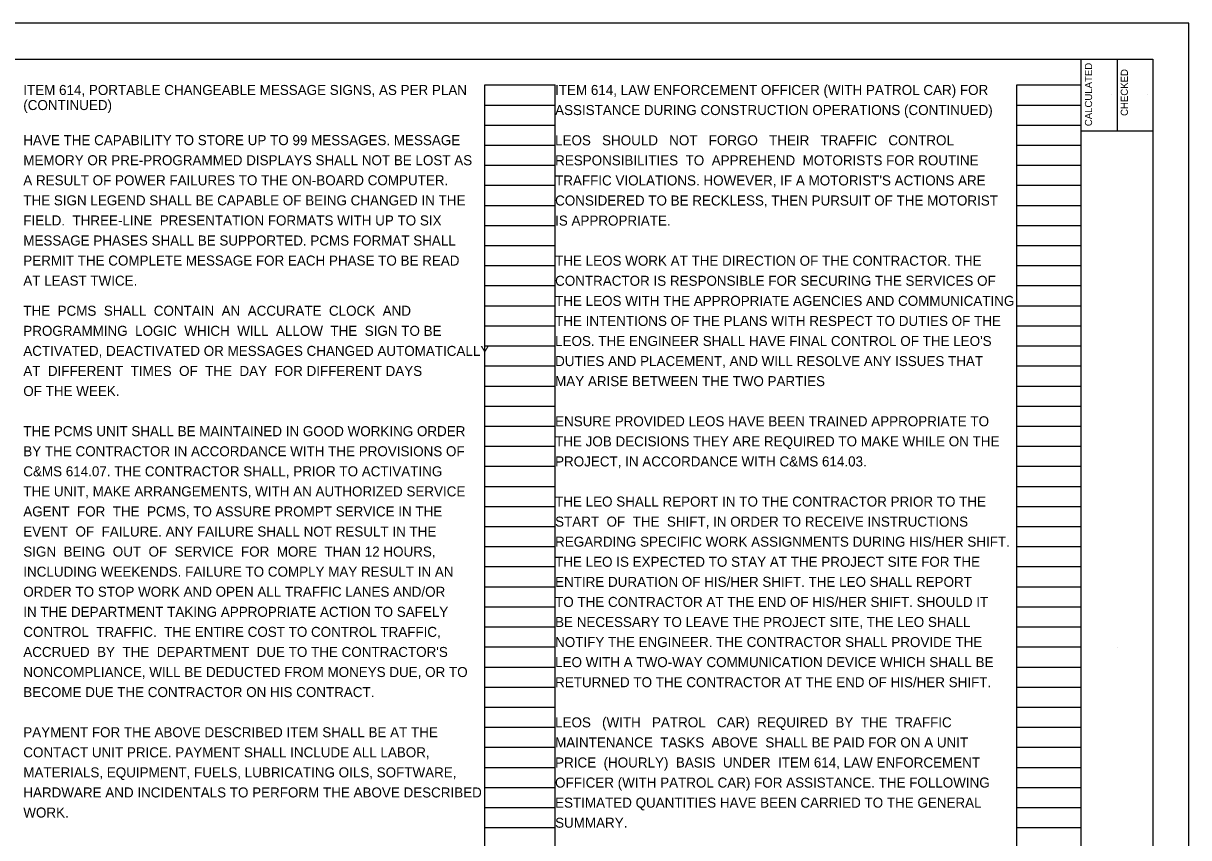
# Model space of a CAD drawing. Extents: x -51 to 34, y 0 to 22.
# Drawn here: x 17.74 to 34, y 10.64 to 22 of the extents above; entities that cross this region are included whole.
import ezdxf

# ---------------------------------------------------------------- set-up
doc = ezdxf.new("R2010")
doc.units = 0
for name, color, linetype in [('SH_Border', 7, 'Continuous'), ('SH_Cut_Line', 7, 'Continuous'), ('SH_Data', 7, 'Continuous'), ('SH_Text', 7, 'Continuous')]:
    doc.layers.add(name, color=color, linetype=linetype)

msp = doc.modelspace()

# ---------------------------------------------------------------- linework, layer by layer
at = {"layer": 'SH_Border'}
for p, q in [((32.5, 0.5), (32.5, 21.5)), ((33, 21.5), (33, 20.5)), ((32.5, 20.5), (33.5, 20.5))]:
    msp.add_line(p, q, dxfattribs=at)
msp.add_lwpolyline([(2, 21.5), (33.5, 21.5), (33.5, 0.5), (2, 0.5)], close=True, dxfattribs=at)
at = {"layer": 'SH_Cut_Line'}
msp.add_lwpolyline([(0, 0), (34, 0), (34, 22), (0, 22)], close=True, dxfattribs=at)
at = {"layer": 'SH_Data'}
for p, q in [((24.18, 0.98), (24.18, 21.14)), ((24.18, 21.14), (25.16, 21.14)), ((25.16, 0.98), (25.16, 21.14)), ((31.6, 0.98), (31.6, 21.14)), ((31.6, 21.14), (32.5, 21.14)), ((32.5, 0.98), (32.5, 21.14)), ((32.92, 21.004), (32.92, 21.004)), ((33.42, 21.004), (33.42, 21.004)), ((24.18, 20.86), (25.16, 20.86)), ((31.6, 20.86), (32.5, 20.86)), ((24.18, 20.58), (25.16, 20.58)), ((31.6, 20.58), (32.5, 20.58)), ((24.18, 20.3), (25.16, 20.3)), ((31.6, 20.3), (32.5, 20.3)), ((24.18, 20.02), (25.16, 20.02)), ((31.6, 20.02), (32.5, 20.02)), ((24.18, 19.74), (25.16, 19.74)), ((31.6, 19.74), (32.5, 19.74)), ((24.18, 19.46), (25.16, 19.46)), ((31.6, 19.46), (32.5, 19.46)), ((24.18, 19.18), (25.16, 19.18)), ((31.6, 19.18), (32.5, 19.18)), ((24.18, 18.9), (25.16, 18.9)), ((31.6, 18.9), (32.5, 18.9)), ((24.18, 18.62), (25.16, 18.62)), ((31.6, 18.62), (32.5, 18.62)), ((24.18, 18.34), (25.16, 18.34)), ((31.6, 18.34), (32.5, 18.34)), ((24.18, 18.06), (25.16, 18.06)), ((31.6, 18.06), (32.5, 18.06)), ((24.18, 17.78), (25.16, 17.78)), ((31.6, 17.78), (32.5, 17.78)), ((24.18, 17.5), (25.16, 17.5)), ((31.6, 17.5), (32.5, 17.5)), ((24.18, 17.22), (25.16, 17.22)), ((31.6, 17.22), (32.5, 17.22)), ((24.18, 16.94), (25.16, 16.94)), ((31.6, 16.94), (32.5, 16.94)), ((24.18, 16.66), (25.16, 16.66)), ((31.6, 16.66), (32.5, 16.66)), ((24.18, 16.38), (25.16, 16.38)), ((31.6, 16.38), (32.5, 16.38)), ((24.18, 16.1), (25.16, 16.1)), ((31.6, 16.1), (32.5, 16.1)), ((24.18, 15.82), (25.16, 15.82)), ((31.6, 15.82), (32.5, 15.82)), ((24.18, 15.54), (25.16, 15.54)), ((31.6, 15.54), (32.5, 15.54)), ((24.18, 15.26), (25.16, 15.26)), ((31.6, 15.26), (32.5, 15.26)), ((24.18, 14.98), (25.16, 14.98)), ((31.6, 14.98), (32.5, 14.98)), ((24.18, 14.7), (25.16, 14.7)), ((31.6, 14.7), (32.5, 14.7)), ((24.18, 14.42), (25.16, 14.42)), ((31.6, 14.42), (32.5, 14.42)), ((24.18, 14.14), (25.16, 14.14)), ((31.6, 14.14), (32.5, 14.14)), ((24.18, 13.86), (25.16, 13.86)), ((31.6, 13.86), (32.5, 13.86)), ((24.18, 13.58), (25.16, 13.58)), ((31.6, 13.58), (32.5, 13.58)), ((24.18, 13.3), (25.16, 13.3)), ((31.6, 13.3), (32.5, 13.3)), ((33, 13.292), (33, 13.292)), ((24.18, 13.02), (25.16, 13.02)), ((31.6, 13.02), (32.5, 13.02)), ((24.18, 12.74), (25.16, 12.74)), ((31.6, 12.74), (32.5, 12.74)), ((24.18, 12.46), (25.16, 12.46)), ((31.6, 12.46), (32.5, 12.46)), ((24.18, 12.18), (25.16, 12.18)), ((31.6, 12.18), (32.5, 12.18)), ((24.18, 11.9), (25.16, 11.9)), ((31.6, 11.9), (32.5, 11.9)), ((24.18, 11.62), (25.16, 11.62)), ((31.6, 11.62), (32.5, 11.62)), ((24.18, 11.34), (25.16, 11.34)), ((31.6, 11.34), (32.5, 11.34)), ((24.18, 11.06), (25.16, 11.06)), ((31.6, 11.06), (32.5, 11.06)), ((24.18, 10.78), (25.16, 10.78)), ((31.6, 10.78), (32.5, 10.78))]:
    msp.add_line(p, q, dxfattribs=at)

# ---------------------------------------------------------------- texts
for s, p in [('CALCULATED', (32.652, 20.565)), ('CHECKED', (33.152, 20.708))]:
    msp.add_text(s, height=0.1, rotation=90, dxfattribs=at).set_placement(p)
at = {"layer": 'SH_Text'}
for s, p in [('ITEM 614, PORTABLE CHANGEABLE MESSAGE SIGNS, AS PER PLAN', (17.74, 21)), ('ITEM 614, LAW ENFORCEMENT OFFICER (WITH PATROL CAR) FOR', (25.16, 21)), ('(CONTINUED)', (17.74, 20.79)), ('ASSISTANCE DURING CONSTRUCTION OPERATIONS (CONTINUED)', (25.16, 20.72)), ('HAVE THE CAPABILITY TO STORE UP TO 99 MESSAGES. MESSAGE', (17.74, 20.3)), ('LEOS   SHOULD   NOT   FORGO   THEIR   TRAFFIC   CONTROL', (25.16, 20.298)), ('MEMORY OR PRE-PROGRAMMED DISPLAYS SHALL NOT BE LOST AS', (17.74, 20.02)), ('RESPONSIBILITIES  TO  APPREHEND  MOTORISTS FOR ROUTINE', (25.16, 20.018)), ('A RESULT OF POWER FAILURES TO THE ON-BOARD COMPUTER.', (17.74, 19.74)), ("TRAFFIC VIOLATIONS. HOWEVER, IF A MOTORIST'S ACTIONS ARE", (25.16, 19.738)), ('THE SIGN LEGEND SHALL BE CAPABLE OF BEING CHANGED IN THE', (17.74, 19.46)), ('CONSIDERED TO BE RECKLESS, THEN PURSUIT OF THE MOTORIST', (25.16, 19.458)), ('FIELD.  THREE-LINE  PRESENTATION FORMATS WITH UP TO SIX', (17.74, 19.18)), ('IS APPROPRIATE.', (25.16, 19.178)), ('MESSAGE PHASES SHALL BE SUPPORTED. PCMS FORMAT SHALL', (17.74, 18.9)), ('PERMIT THE COMPLETE MESSAGE FOR EACH PHASE TO BE READ', (17.74, 18.62)), ('THE LEOS WORK AT THE DIRECTION OF THE CONTRACTOR. THE', (25.16, 18.618)), ('AT LEAST TWICE.', (17.74, 18.34)), ('CONTRACTOR IS RESPONSIBLE FOR SECURING THE SERVICES OF', (25.16, 18.338)), ('THE  PCMS  SHALL  CONTAIN  AN  ACCURATE  CLOCK  AND', (17.74, 17.92)), ('THE LEOS WITH THE APPROPRIATE AGENCIES AND COMMUNICATING', (25.16, 18.058)), ('THE INTENTIONS OF THE PLANS WITH RESPECT TO DUTIES OF THE', (25.16, 17.778)), ('PROGRAMMING  LOGIC  WHICH  WILL  ALLOW  THE  SIGN TO BE', (17.74, 17.64)), ("LEOS. THE ENGINEER SHALL HAVE FINAL CONTROL OF THE LEO'S", (25.16, 17.498)), ('ACTIVATED, DEACTIVATED OR MESSAGES CHANGED AUTOMATICALLY', (17.74, 17.36)), ('DUTIES AND PLACEMENT, AND WILL RESOLVE ANY ISSUES THAT', (25.16, 17.218)), ('AT  DIFFERENT  TIMES  OF  THE  DAY  FOR DIFFERENT DAYS', (17.74, 17.08)), ('MAY ARISE BETWEEN THE TWO PARTIES', (25.16, 16.938)), ('OF THE WEEK.', (17.74, 16.8)), ('ENSURE PROVIDED LEOS HAVE BEEN TRAINED APPROPRIATE TO', (25.16, 16.378)), ('THE PCMS UNIT SHALL BE MAINTAINED IN GOOD WORKING ORDER', (17.74, 16.24)), ('BY THE CONTRACTOR IN ACCORDANCE WITH THE PROVISIONS OF', (17.74, 15.96)), ('THE JOB DECISIONS THEY ARE REQUIRED TO MAKE WHILE ON THE', (25.16, 16.098)), ('PROJECT, IN ACCORDANCE WITH C&MS 614.03.', (25.16, 15.818)), ('C&MS 614.07. THE CONTRACTOR SHALL, PRIOR TO ACTIVATING', (17.74, 15.68)), ('THE UNIT, MAKE ARRANGEMENTS, WITH AN AUTHORIZED SERVICE', (17.74, 15.4)), ('THE LEO SHALL REPORT IN TO THE CONTRACTOR PRIOR TO THE', (25.16, 15.258)), ('AGENT  FOR  THE  PCMS, TO ASSURE PROMPT SERVICE IN THE', (17.74, 15.12)), ('EVENT  OF  FAILURE. ANY FAILURE SHALL NOT RESULT IN THE', (17.74, 14.84)), ('START  OF  THE  SHIFT, IN ORDER TO RECEIVE INSTRUCTIONS', (25.16, 14.978)), ('REGARDING SPECIFIC WORK ASSIGNMENTS DURING HIS/HER SHIFT.', (25.16, 14.698)), ('SIGN  BEING  OUT  OF  SERVICE  FOR  MORE  THAN 12 HOURS,', (17.74, 14.56)), ('THE LEO IS EXPECTED TO STAY AT THE PROJECT SITE FOR THE', (25.16, 14.418)), ('INCLUDING WEEKENDS. FAILURE TO COMPLY MAY RESULT IN AN', (17.74, 14.28)), ('ORDER TO STOP WORK AND OPEN ALL TRAFFIC LANES AND/OR', (17.74, 14)), ('ENTIRE DURATION OF HIS/HER SHIFT. THE LEO SHALL REPORT', (25.16, 14.138)), ('TO THE CONTRACTOR AT THE END OF HIS/HER SHIFT. SHOULD IT', (25.16, 13.858)), ('IN THE DEPARTMENT TAKING APPROPRIATE ACTION TO SAFELY', (17.74, 13.72)), ('BE NECESSARY TO LEAVE THE PROJECT SITE, THE LEO SHALL', (25.16, 13.578)), ('CONTROL  TRAFFIC.  THE ENTIRE COST TO CONTROL TRAFFIC,', (17.74, 13.44)), ('NOTIFY THE ENGINEER. THE CONTRACTOR SHALL PROVIDE THE', (25.16, 13.298)), ("ACCRUED  BY  THE  DEPARTMENT  DUE TO THE CONTRACTOR'S", (17.74, 13.16)), ('NONCOMPLIANCE, WILL BE DEDUCTED FROM MONEYS DUE, OR TO', (17.74, 12.88)), ('LEO WITH A TWO-WAY COMMUNICATION DEVICE WHICH SHALL BE', (25.16, 13.018)), ('RETURNED TO THE CONTRACTOR AT THE END OF HIS/HER SHIFT.', (25.16, 12.738)), ('BECOME DUE THE CONTRACTOR ON HIS CONTRACT.', (17.74, 12.6)), ('LEOS   (WITH   PATROL   CAR)  REQUIRED  BY  THE  TRAFFIC', (25.16, 12.178)), ('PAYMENT FOR THE ABOVE DESCRIBED ITEM SHALL BE AT THE ', (17.74, 12.04)), ('MAINTENANCE  TASKS  ABOVE  SHALL BE PAID FOR ON A UNIT', (25.16, 11.898)), ('CONTACT UNIT PRICE. PAYMENT SHALL INCLUDE ALL LABOR,', (17.74, 11.76)), ('PRICE  (HOURLY)  BASIS  UNDER  ITEM 614, LAW ENFORCEMENT', (25.16, 11.618)), ('MATERIALS, EQUIPMENT, FUELS, LUBRICATING OILS, SOFTWARE,', (17.74, 11.48)), ('OFFICER (WITH PATROL CAR) FOR ASSISTANCE. THE FOLLOWING', (25.16, 11.338)), ('HARDWARE AND INCIDENTALS TO PERFORM THE ABOVE DESCRIBED', (17.74, 11.2)), ('WORK.', (17.74, 10.92)), ('ESTIMATED QUANTITIES HAVE BEEN CARRIED TO THE GENERAL', (25.16, 11.058)), ('SUMMARY.', (25.16, 10.778))]:
    msp.add_text(s, height=0.14, dxfattribs=at).set_placement(p)

doc.saveas('drawing.dxf')
